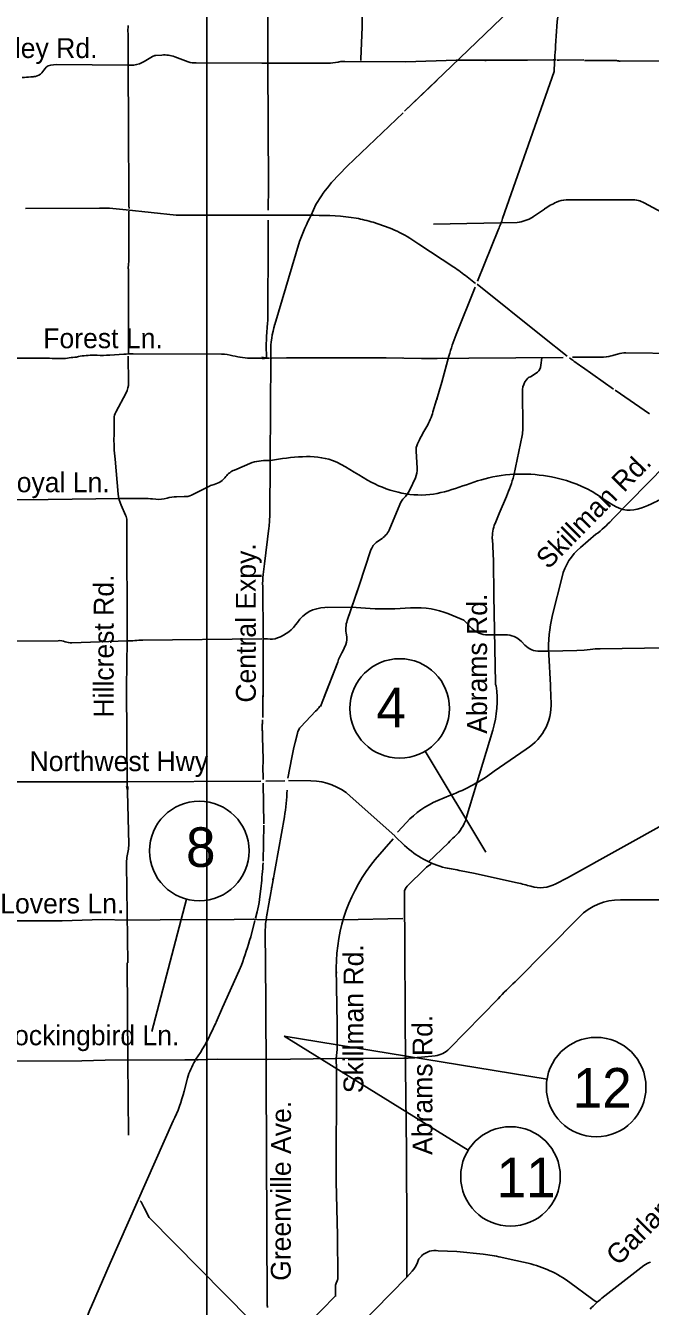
# Model space of a CAD drawing. Extents: x 105094 to 105814, y -291615 to -291123.
# Drawn here: x 105448.1 to 105486.2, y -291448 to -291369.9 of the extents above; entities that cross this region are included whole.
import ezdxf

# ---------------------------------------------------------------- set-up
doc = ezdxf.new("R2010")
doc.units = 0
doc.layers.add('G_BORDER', color=7, linetype='Continuous')
doc.layers.add('G_MAP', color=7, linetype='Continuous')

msp = doc.modelspace()

# ---------------------------------------------------------------- linework, layer by layer
at = {"layer": 'G_BORDER'}
for p, q in [((105459.139, -291158.398), (105459.139, -291578.398)), ((105476.145, -291420.288), (105472.461, -291414.129)), ((105455.785, -291431.225), (105457.913, -291423.154)), ((105463.865, -291431.513), (105479.882, -291434.137)), ((105463.865, -291431.513), (105475.077, -291438.476))]:
    msp.add_line(p, q, dxfattribs=at)
for centre in [(105470.903, -291411.525), (105458.686, -291420.219), (105482.877, -291434.627), (105477.655, -291440.078)]:
    msp.add_circle(centre, 3.035, dxfattribs=at)
at = {"layer": 'G_MAP'}
for p, q in [((105474.575, -291371.851), (105477.633, -291368.905)), ((105449.967, -291372.236), (105454.349, -291372.277)), ((105456.044, -291371.689), (105456.396, -291371.661)), ((105457.192, -291371.769), (105458.018, -291372.071)), ((105467.148, -291372.091), (105467.221, -291372.077)), ((105467.548, -291372.064), (105471.274, -291372.067)), ((105468.533, -291371.996), (105468.529, -291371.893)), ((105471.193, -291375.09), (105474.575, -291371.851)), ((105474.348, -291371.969), (105471.274, -291372.067)), ((105474.348, -291371.969), (105478.686, -291371.967)), ((105476.135, -291371.96), (105476.132, -291372.025)), ((105478.686, -291371.967), (105480.259, -291371.96)), ((105480.259, -291371.96), (105480.43, -291371.96)), ((105480.492, -291371.967), (105480.621, -291371.973)), ((105480.621, -291371.973), (105482.119, -291371.957)), ((105482.168, -291371.993), (105483.98, -291371.993)), ((105484.337, -291372.036), (105487.826, -291372.012)), ((105480.317, -291372.658), (105477.174, -291381.633)), ((105471.193, -291375.09), (105473.18, -291373.184)), ((105471.193, -291375.09), (105473.18, -291373.184)), ((105471.119, -291375.196), (105467.69, -291378.436)), ((105467.69, -291378.436), (105466.754, -291379.439)), ((105465.799, -291380.781), (105465.504, -291381.437)), ((105485.042, -291380.486), (105481.051, -291380.499)), ((105489.337, -291382.576), (105485.809, -291380.678)), ((105452.598, -291380.994), (105448.103, -291381.018)), ((105457.271, -291381.436), (105454.236, -291381.11)), ((105461.673, -291381.439), (105457.271, -291381.436)), ((105479.719, -291381.054), (105479.006, -291381.545)), ((105470.26, -291382.198), (105469.294, -291381.862)), ((105478.063, -291381.885), (105472.963, -291381.969)), ((105476.916, -291382.285), (105475.647, -291385.466)), ((105464.8, -291383.032), (105463.289, -291388.09)), ((105472.065, -291383.199), (105471.516, -291382.828)), ((105474.197, -291384.594), (105472.065, -291383.199)), ((105475.531, -291385.595), (105475.014, -291385.195)), ((105475.505, -291385.821), (105474.346, -291388.705)), ((105479.632, -291388.851), (105475.631, -291385.647)), ((105462.786, -291388.824), (105462.836, -291388.024)), ((105462.774, -291390.139), (105462.771, -291389.355)), ((105481.111, -291390.042), (105479.632, -291388.851)), ((105440.514, -291390.176), (105449.211, -291390.156)), ((105452.278, -291389.975), (105452.46, -291389.978)), ((105453.228, -291389.965), (105454.081, -291389.92)), ((105454.369, -291391.654), (105454.358, -291390.04)), ((105454.665, -291389.894), (105460.041, -291389.914)), ((105461.922, -291390.152), (105462.506, -291390.146)), ((105462.761, -291390.146), (105462.965, -291390.146)), ((105463.039, -291390.214), (105463.02, -291393.153)), ((105463.039, -291389.797), (105463.039, -291389.984)), ((105463.039, -291389.984), (105463.039, -291390.214)), ((105480.866, -291390.104), (105472.236, -291390.175)), ((105473.526, -291390.164), (105472.236, -291390.175)), ((105473.526, -291390.164), (105472.236, -291390.175)), ((105473.18, -291390.167), (105472.236, -291390.175)), ((105473.18, -291390.167), (105472.236, -291390.175)), ((105483.169, -291390.097), (105481.441, -291390.091)), ((105484.186, -291389.902), (105483.801, -291390.011)), ((105488.846, -291389.877), (105484.693, -291389.835)), ((105483.937, -291392.041), (105482.036, -291390.709)), ((105479.224, -291391.073), (105478.88, -291391.302)), ((105453.596, -291393.445), (105454.225, -291392.274)), ((105478.395, -291392.07), (105478.402, -291394.468)), ((105486.12, -291393.559), (105484.034, -291392.103)), ((105463.02, -291393.153), (105462.997, -291396.514)), ((105472.93, -291393.426), (105473.154, -291392.697)), ((105453.49, -291394.916), (105453.5, -291393.831)), ((105478.365, -291394.881), (105477.862, -291397.321)), ((105453.499, -291395.594), (105453.49, -291395.359)), ((105471.984, -291395.389), (105472.106, -291395.139)), ((105453.741, -291398.442), (105453.551, -291396.311)), ((105471.969, -291396.861), (105471.898, -291395.826)), ((105461.916, -291396.522), (105460.827, -291396.978)), ((105462.997, -291396.514), (105462.984, -291399.626)), ((105487.099, -291396.685), (105483.821, -291400.044)), ((105459.311, -291397.957), (105458.208, -291398.514)), ((105459.601, -291397.859), (105459.447, -291397.903)), ((105471.518, -291398.186), (105471.857, -291397.464)), ((105456.045, -291398.762), (105455.838, -291398.746)), ((105457.762, -291398.594), (105457.292, -291398.609)), ((105454.199, -291399.728), (105453.922, -291399.125)), ((105470.307, -291400.554), (105470.976, -291398.945)), ((105462.927, -291400.521), (105462.661, -291402.702)), ((105469.539, -291401.346), (105469.824, -291401.149)), ((105482.865, -291400.9), (105481.919, -291401.697)), ((105462.661, -291402.702), (105462.587, -291403.351)), ((105480.798, -291403.496), (105480.22, -291405.821)), ((105462.552, -291404.081), (105462.574, -291407.185)), ((105467.951, -291405.35), (105466.34, -291405.372)), ((105467.951, -291405.35), (105466.495, -291405.37)), ((105467.951, -291405.35), (105466.495, -291405.37)), ((105474.814, -291406.144), (105475.305, -291406.638)), ((105450.086, -291407.395), (105442.801, -291407.424)), ((105454.31, -291407.401), (105450.91, -291407.522)), ((105462.503, -291407.285), (105455.244, -291407.355)), ((105462.574, -291407.385), (105462.57, -291410.814)), ((105462.574, -291407.185), (105462.574, -291407.385)), ((105462.852, -291407.285), (105462.639, -291407.285)), ((105476.261, -291407.033), (105477.329, -291407.026)), ((105467.415, -291408.063), (105467.61, -291407.619)), ((105467.415, -291408.063), (105467.61, -291407.619)), ((105467.415, -291408.063), (105467.61, -291407.619)), ((105478.323, -291407.445), (105478.534, -291407.664)), ((105466.075, -291411.399), (105467.121, -291408.693)), ((105466.301, -291410.814), (105467.121, -291408.693)), ((105466.301, -291410.814), (105467.121, -291408.693)), ((105479.99, -291408.242), (105480.091, -291410.11)), ((105462.572, -291409.355), (105462.568, -291412.077)), ((105462.572, -291409.355), (105462.57, -291410.814)), ((105454.249, -291410.25), (105454.294, -291416.292)), ((105454.249, -291410.25), (105454.253, -291410.814)), ((105454.249, -291410.25), (105454.253, -291410.814)), ((105480.104, -291410.879), (105480.091, -291410.111)), ((105465.765, -291411.696), (105464.874, -291412.655)), ((105476.57, -291412.845), (105474.956, -291418.222)), ((105476.658, -291415.361), (105478.609, -291414.002)), ((105462.568, -291415.035), (105462.574, -291415.865)), ((105463.898, -291415.936), (105462.742, -291415.959)), ((105465.494, -291415.943), (105464.128, -291415.93)), ((105454.317, -291416.618), (105454.389, -291419.795)), ((105462.578, -291416.091), (105462.616, -291418.558)), ((105473.218, -291417.143), (105474, -291416.814)), ((105470.609, -291419.288), (105467.887, -291416.867)), ((105463.876, -291418.131), (105462.778, -291424.248)), ((105487.451, -291418.332), (105481.125, -291421.859)), ((105462.613, -291418.652), (105462.574, -291420.838)), ((105470.771, -291419.081), (105471.326, -291418.475)), ((105469.411, -291420.748), (105470.512, -291419.485)), ((105470.6, -291419.32), (105471.203, -291419.89)), ((105473.874, -291419.73), (105472.637, -291420.909)), ((105454.254, -291421.023), (105454.336, -291427.049)), ((105471.358, -291422.372), (105472.446, -291421.291)), ((105474.643, -291421.429), (105475.408, -291421.577)), ((105463.136, -291421.949), (105463.207, -291421.969)), ((105475.408, -291421.577), (105478.068, -291422.162)), ((105480.423, -291422.227), (105481.125, -291421.859)), ((105462.453, -291422.355), (105462.356, -291423.179)), ((105463.13, -291422.508), (105463.046, -291422.495)), ((105471.252, -291433.468), (105471.187, -291422.773)), ((105462.93, -291423.147), (105462.991, -291423.17)), ((105484.35, -291423.199), (105486.735, -291423.209)), ((105461.983, -291424.391), (105460.814, -291424.397)), ((105462.077, -291424.462), (105461.822, -291425.466)), ((105462.203, -291424.397), (105461.974, -291424.391)), ((105462.212, -291423.936), (105462.109, -291424.329)), ((105467.464, -291424.416), (105462.2, -291424.397)), ((105462.862, -291424.039), (105462.775, -291424.009)), ((105471.1, -291424.338), (105467.461, -291424.416)), ((105477.94, -291428.214), (105481.852, -291424.24)), ((105462.704, -291425.059), (105462.752, -291429.393)), ((105461.111, -291427.52), (105460.094, -291429.774)), ((105461.254, -291427.178), (105461.111, -291427.52)), ((105467.083, -291427.636), (105466.983, -291427.655)), ((105473.924, -291432.294), (105476.897, -291429.238)), ((105460.094, -291429.774), (105459.707, -291430.675)), ((105462.752, -291429.393), (105462.82, -291447.834)), ((105457.811, -291432.971), (105458.315, -291432.965)), ((105458.315, -291432.965), (105458.612, -291432.968)), ((105458.754, -291432.519), (105458.486, -291432.92)), ((105458.612, -291432.968), (105459.791, -291432.932)), ((105472.226, -291432.797), (105473.067, -291432.709)), ((105457.969, -291434.082), (105457.756, -291434.87)), ((105457.094, -291436.692), (105453.264, -291445.373)), ((105472.25, -291444.91), (105472.224, -291444.935)), ((105453.264, -291445.373), (105452.115, -291447.991)), ((105483.231, -291447.504), (105485.79, -291445.517)), ((105467.034, -291446.583), (105467.097, -291446.441)), ((105466.993, -291447.397), (105466.993, -291446.845)), ((105481.274, -291446.541), (105482.601, -291447.526)), ((105466.992, -291447.365), (105465.239, -291449.141))]:
    msp.add_line(p, q, dxfattribs=at)
for points in [[(105462.887, -291381.123), (105462.907, -291379.702), (105462.862, -291372.19), (105462.839, -291365.796)], [(105468.529, -291371.893), (105468.607, -291369.965), (105468.594, -291367.264)], [(105454.388, -291380.316), (105454.368, -291376.159), (105454.342, -291372.239), (105454.342, -291370.34)], [(105455.036, -291372.188), (105455.127, -291372.155), (105455.337, -291372.045), (105455.825, -291371.758)], [(105458.492, -291372.129), (105462.494, -291372.164), (105466.521, -291372.151)], [(105454.388, -291384.285), (105454.391, -291383.736), (105454.394, -291381.188)], [(105462.868, -291387.343), (105462.894, -291383.164), (105462.884, -291381.727)], [(105454.362, -291389.927), (105454.368, -291385.557), (105454.362, -291384.711)], [(105449.886, -291390.182), (105450.541, -291390.169), (105450.871, -291390.117)], [(105463.104, -291390.146), (105463.998, -291390.133), (105470.086, -291390.13), (105471.08, -291390.15)], [(105469.837, -291390.13), (105470.086, -291390.13), (105471.08, -291390.15)], [(105469.837, -291390.13), (105470.086, -291390.13), (105472.236, -291390.175)], [(105473.901, -291390.025), (105473.46, -291391.628), (105473.147, -291392.726)], [(105473.223, -291392.46), (105473.147, -291392.726)], [(105473.223, -291392.46), (105473.147, -291392.726)], [(105473.18, -291392.613), (105473.147, -291392.726)], [(105473.18, -291392.613), (105473.147, -291392.726)], [(105455.298, -291398.714), (105453.848, -291398.724), (105449.472, -291398.776), (105443.595, -291398.798)], [(105477.42, -291398.587), (105476.955, -291399.634), (105476.713, -291400.232)], [(105454.249, -291410.25), (105454.294, -291407.398), (105454.271, -291400.069)], [(105467.704, -291406.154), (105468.442, -291403.971), (105469.126, -291401.899)], [(105476.548, -291401.202), (105476.609, -291402.524), (105476.648, -291404.636), (105476.732, -291409.977)], [(105467.704, -291406.154), (105468.34, -291404.273)], [(105467.704, -291406.154), (105468.34, -291404.273)], [(105479.44, -291408.039), (105479.988, -291408.027), (105481.699, -291407.982), (105482.148, -291407.959), (105482.52, -291407.927)], [(105483.13, -291407.888), (105487.173, -291407.827), (105488.485, -291407.785), (105493.093, -291407.704), (105495.115, -291407.662), (105497.033, -291407.681)], [(105464.668, -291413.025), (105464.451, -291413.911), (105464.318, -291414.518), (105464.092, -291415.788)], [(105464.668, -291413.025), (105464.524, -291413.613)], [(105464.668, -291413.025), (105464.524, -291413.613)], [(105462.448, -291415.962), (105454.301, -291416.011), (105442.268, -291416.005)], [(105460.814, -291424.397), (105456.296, -291424.413), (105454.3, -291424.436), (105452.77, -291424.404), (105450.331, -291424.488), (105445.991, -291424.491)], [(105454.362, -291437.561), (105454.323, -291432.997), (105454.291, -291427.039)], [(105467.054, -291433.555), (105467.038, -291432.89), (105467.093, -291432.335), (105467.092, -291430.791), (105467.038, -291427.345)], [(105441.075, -291433.014), (105441.566, -291433.046), (105451.529, -291433.03), (105452.947, -291432.988), (105457.811, -291432.971)], [(105459.791, -291432.932), (105462.836, -291432.939), (105467.021, -291432.884), (105471.146, -291432.864)], [(105467.132, -291446.245), (105467.118, -291443.68), (105467.034, -291440.376), (105467.054, -291433.555)], [(105471.339, -291446.199), (105471.327, -291443.641), (105471.307, -291438.535), (105471.252, -291433.468)], [(105455.331, -291442.001), (105455.15, -291441.63), (105455.085, -291441.575)], [(105462.839, -291449.907), (105461.796, -291448.822), (105455.634, -291442.573), (105455.331, -291442.001)], [(105473.251, -291444.623), (105474.385, -291444.652), (105475.993, -291444.816)], [(105477.072, -291445.001), (105477.695, -291445.136), (105478.727, -291445.377)], [(105471.669, -291445.853), (105471.33, -291446.221), (105468.414, -291449.206), (105465.61, -291451.938), (105463.22, -291454.38), (105458.379, -291459.237), (105456.07, -291461.521)]]:
    msp.add_lwpolyline(points, dxfattribs=at)
for centre, radius, start, end in [((105456.987, -291370.192), 2.649, 172.90765, 183.19615), ((105454.476, -291370.637), 1.648, 265.57828, 289.84555), ((105456.085, -291372.2), 0.512, 94.60671, 120.42732), ((105456.548, -291373.53), 1.876, 69.90353, 94.63636), ((105458.358, -291371.256), 0.883, 247.31491, 278.72622), ((105466.509, -291368.734), 3.417, 270.19641, 280.77032), ((105467.407, -291372.647), 0.6, 76.48657, 108.05496), ((105483.979, -291373.11), 1.117, 76.96772, 89.90709), ((105484.335, -291371.657), 0.379, 254.0581, 270.35405), ((105447.854, -291368.986), 4.039, 270.59303, 278.00387), ((105473.216, -291385.048), 8.557, 139.03718, 150.08606), ((105461.352, -291380.479), 6.966, 178.65839, 184.48031), ((105482.347, -291384.866), 4.631, 114.06028, 124.5774), ((105481.057, -291381.858), 1.358, 90.24609, 116.09824), ((105485.047, -291382.093), 1.608, 61.71655, 90.19845), ((105452.658, -291391.793), 10.799, 81.59999, 90.31773), ((105475.855, -291386.965), 11.734, 151.89398, 160.4146), ((105473.209, -291380.439), 4.141, 333.53368, 343.25265), ((105477.661, -291379.286), 2.63, 278.79374, 300.7632), ((105466.271, -291391.723), 10.327, 59.47499, 67.27768), ((105456.631, -291384.635), 2.271, 171.13441, 181.92475), ((105466.219, -291396.302), 14.167, 51.62792, 55.72999), ((105459.104, -291387.506), 3.768, 352.09201, 2.48086), ((105469.007, -291389.797), 5.968, 163.37288, 179.99929), ((105470.949, -291389.33), 8.178, 176.44883, 180.17709), ((105485.723, -291393.275), 12.26, 158.11332, 164.62616), ((105449.099, -291401.924), 11.769, 86.16477, 89.45362), ((105450.848, -291388.203), 1.914, 270.69247, 284.1748), ((105452.187, -291394.458), 4.485, 88.82709, 101.18931), ((105452.764, -291385.221), 4.767, 266.33968, 275.58838), ((105454.576, -291394.499), 4.606, 88.89074, 96.17397), ((105460.037, -291392.665), 2.751, 75.23863, 89.9255), ((105461.877, -291385.681), 4.471, 255.24282, 270.58222), ((105462.509, -291390.486), 0.383, 70.79201, 90.00362), ((105462.509, -291389.806), 0.383, 270.00369, 289.21531), ((105462.761, -291389.763), 0.383, 250.79211, 270.00372), ((105462.761, -291390.529), 0.383, 90.00365, 109.21526), ((105474.054, -291389.668), 5.526, 348.92208, 355.24674), ((105494.064, -291373.555), 20.951, 232.30477, 234.96455), ((105483.177, -291387.801), 2.296, 269.78609, 285.76707), ((105484.674, -291391.631), 1.796, 89.40072, 105.76144), ((105478.879, -291390.554), 0.623, 303.54832, 343.59133), ((105453.143, -291391.694), 1.227, 331.83134, 1.88438), ((105479.309, -291392.086), 0.914, 138.19423, 179.02054), ((105478.922, -291391.633), 0.334, 97.36085, 152.02943), ((105454.31, -291393.828), 0.811, 151.85089, 180.22784), ((105467.808, -291391.856), 5.357, 332.48801, 342.96051), ((105460.639, -291395.137), 7.153, 178.22966, 181.77441), ((105479.291, -291398.643), 7.994, 147.35889, 154.00196), ((105476.595, -291394.515), 1.807, 348.33204, 1.50301), ((105464.726, -291395.146), 11.235, 182.28917, 185.95544), ((105472.76, -291395.768), 0.864, 154.00761, 183.88157), ((105462.854, -291399.817), 3.426, 87.11339, 105.899), ((105461.33, -291398.176), 1.299, 112.74899, 142.17138), ((105470.753, -291396.946), 1.219, 334.85905, 4.01293), ((105459.664, -291398.657), 0.784, 106.08977, 116.78922), ((105459.225, -291396.554), 1.358, 286.08478, 322.60226), ((105464.016, -291393.193), 14.449, 338.07599, 343.39581), ((105455.817, -291398.256), 2.084, 185.09516, 204.61278), ((105455.366, -291402.099), 3.386, 81.99849, 91.15104), ((105456.193, -291396.787), 1.98, 265.71015, 285.43324), ((105457.371, -291401.063), 2.455, 91.84194, 105.38441), ((105457.87, -291397.919), 0.684, 260.93851, 299.59859), ((105471.638, -291399.221), 0.717, 133.32181, 157.377), ((105469.985, -291397.466), 1.694, 313.27668, 334.86937), ((105455.087, -291399.568), 7.897, 353.07253, 359.58061), ((105453.48, -291400.058), 0.791, 359.21568, 24.65603), ((105478.847, -291401.095), 2.302, 157.98058, 182.67386), ((105477.381, -291393.812), 8.962, 307.73254, 315.94253), ((105469.054, -291400.032), 1.357, 304.584, 337.38831), ((105470.155, -291402.238), 1.084, 124.60637, 161.75987), ((105484.131, -291404.323), 3.434, 130.11499, 166.05589), ((105466.187, -291403.892), 3.64, 171.45435, 182.97493), ((105466.368, -291407.425), 2.054, 90.78567, 145.9361), ((105488.183, -291407.8), 8.205, 166.04431, 183.09138), ((105462.592, -291404.872), 2.505, 290.17392, 325.93594), ((105469.224, -291406.668), 1.605, 161.32798, 193.38978), ((105469.224, -291406.668), 1.605, 161.32798, 193.38978), ((105469.224, -291406.668), 1.605, 161.32798, 193.38978), ((105476.253, -291405.695), 1.337, 224.8513, 270.34399), ((105450.198, -291408.225), 0.837, 67.46724, 97.69655), ((105454.453, -291405.005), 2.401, 266.58731, 277.09845), ((105455.27, -291411.552), 4.198, 90.35695, 97.11919), ((105463.045, -291406.185), 1.117, 260.03333, 291.57314), ((105466.776, -291407.251), 0.912, 336.24808, 13.40225), ((105466.776, -291407.251), 0.912, 336.24808, 13.40225), ((105466.776, -291407.251), 0.912, 336.24808, 13.40225), ((105477.338, -291408.392), 1.366, 43.89807, 90.36509), ((105450.878, -291406.587), 0.936, 247.47718, 271.99599), ((105469.769, -291409.545), 2.781, 147.80898, 162.16191), ((105469.769, -291409.545), 2.781, 147.80898, 162.16191), ((105469.769, -291409.545), 2.781, 147.80898, 162.16191), ((105479.414, -291406.817), 1.222, 223.89247, 271.22299), ((105483.039, -291411.274), 3.387, 88.45449, 98.81442), ((105470.412, -291410.997), 6.43, 343.29267, 7.66313), ((105477.008, -291409.978), 0.276, 179.87024, 215.72931), ((105476.957, -291411.292), 3.174, 301.35754, 7.46798), ((105465.036, -291410.761), 1.186, 307.94073, 327.81268), ((105482.509, -291412.654), 19.981, 178.75432, 182.99685), ((105482.509, -291412.654), 19.981, 178.75432, 182.19431), ((105482.509, -291412.654), 19.981, 178.75432, 182.19431), ((105465.439, -291413.212), 0.794, 135.39347, 166.31756), ((105465.439, -291413.212), 0.794, 135.39347, 166.31756), ((105465.439, -291413.212), 0.794, 135.39347, 166.31756), ((105437.774, -291414.606), 24.798, 359.00816, 2.09767), ((105465.458, -291419.598), 3.655, 48.34842, 89.44205), ((105470.222, -291406.746), 10.754, 290.56899, 306.76143), ((105454.888, -291416.251), 0.638, 183.96491, 198.8223), ((105453.681, -291416.662), 0.638, 3.96485, 18.82224), ((105454.953, -291416.574), 0.638, 169.10755, 183.96494), ((105453.701, -291416.333), 0.638, 349.10746, 3.96485), ((105453.916, -291416.342), 10.12, 349.81782, 359.00696), ((105475.316, -291422.133), 5.413, 112.8069, 137.48618), ((105472.696, -291417.571), 2.353, 310.88321, 343.92179), ((105452.791, -291419.836), 1.599, 346.61188, 1.49709), ((105475.046, -291415.816), 5.6, 226.66775, 255.92269), ((105475.996, -291421.382), 2.689, 130.89232, 142.0945), ((105457.625, -291420.99), 3.371, 166.56736, 180.5649), ((105439.795, -291419.687), 22.814, 353.28374, 356.83907), ((105477.341, -291427.326), 10.303, 140.31955, 180.1064), ((105473.444, -291422.295), 1.416, 115.94892, 134.81454), ((105471.132, -291437.415), 16.367, 77.61161, 81.02915), ((105475.423, -291434.123), 12.249, 73.51415, 77.53171), ((105479.477, -291420.427), 2.034, 253.48533, 297.71202), ((105471.769, -291422.785), 0.582, 134.85304, 178.86316), ((105456.862, -291422.532), 5.531, 345.29163, 353.27819), ((105484.336, -291426.685), 3.485, 89.75986, 135.45428), ((105471.822, -291425.486), 9.128, 172.20856, 177.31954), ((105436.375, -291417.966), 26.529, 339.68147, 343.57725), ((105484.995, -291436.446), 10.841, 130.59496, 138.32526), ((105445.907, -291424.714), 15.032, 328.71834, 336.63619), ((105472.922, -291431.319), 1.398, 275.95994, 315.77442), ((105462.384, -291435.35), 4.593, 149.46584, 163.96966), ((105470.981, -291421.454), 11.411, 270.82668, 276.26367), ((105449.501, -291432.901), 8.486, 333.46841, 346.58179), ((105472.851, -291445.604), 0.917, 133.15148, 162.01807), ((105473.032, -291445.745), 1.144, 78.94796, 133.13375), ((105474.416, -291457.306), 12.589, 77.82187, 82.80391), ((105470.614, -291444.882), 1.434, 317.38607, 342.16211), ((105477.13, -291452.235), 7.042, 53.95919, 76.89268), ((105486.525, -291446.441), 1.181, 107.02262, 128.47148), ((105466.701, -291446.269), 0.431, 336.51562, 3.22901), ((105467.426, -291446.78), 0.438, 153.28963, 188.47448), ((105466.386, -291454.248), 15.582, 156.3243, 163.25405), ((105463.665, -291447.84), 0.844, 179.53905, 195.37593), ((105486.614, -291451.853), 5.51, 127.87873, 138.00905), ((105483.235, -291446.89), 0.899, 225.0986, 251.24528)]:
    msp.add_arc(centre, radius, start, end, dxfattribs=at)
for points in [[(105485.111, -291359.381), (105481.067, -291366.438), (105480.399, -291371.098), (105480.317, -291372.658)], [(105449.967, -291372.236), (105449.354, -291372.405), (105449.088, -291372.755), (105448.696, -291372.963), (105448.416, -291372.985)], [(105469.294, -291381.862), (105468.252, -291381.616), (105465.675, -291381.437), (105461.673, -291381.439)], [(105463.027, -291396.395), (105466.797, -291396.395), (105468.945, -291397.601), (105472.732, -291398.475), (105476.336, -291397.455), (105480.413, -291397.455), (105482.925, -291398.475), (105484.746, -291399.423), (105486.457, -291398.949), (105487.284, -291398.616), (105488.378, -291398.636)], [(105474.814, -291406.144), (105472.827, -291405.452), (105470.279, -291405.452), (105467.951, -291405.35)]]:
    msp.add_spline(points, degree=3, dxfattribs=at)

# ---------------------------------------------------------------- texts
at = {"layer": 'G_BORDER'}
for s, p in [('4', (105469.484, -291412.67)), ('8', (105457.879, -291421.194)), ('12', (105481.45, -291435.879)), ('11', (105476.809, -291441.348))]:
    msp.add_text(s, height=2.416, dxfattribs=at).set_placement(p)
at = {"layer": 'G_MAP'}
for s, height, p in [('Spring Valley Rd.', 1.21107, (105439.971, -291371.842)), ('Forest Ln.', 1.2111, (105449.174, -291389.545)), ('Royal Ln.', 1.2111, (105446.389, -291398.334)), ('Northwest Hwy', 1.21107, (105448.339, -291415.349)), ('Lovers Ln.', 1.2111, (105446.554, -291424.029)), ('Mockingbird Ln.', 1.21107, (105446.045, -291432.074))]:
    msp.add_text(s, height=height, dxfattribs=at).set_placement(p)
for s, height, rotation, p in [('Skillman Rd.', 1.21107, 45.49919, (105479.96, -291403.08)), ('Central Expy.', 1.21107, 90, (105462.133, -291411.169)), ('Hillcrest Rd.', 1.21107, 90, (105453.468, -291412.082)), ('Abrams Rd.', 1.2111, 90, (105476.225, -291413.07)), ('Skillman Rd.', 1.21107, 90, (105468.69, -291435.001)), ('Abrams Rd.', 1.2111, 90, (105472.895, -291438.763)), ('Greenville Ave.', 1.21107, 89.90288, (105464.259, -291446.447)), ('Garland Rd.', 1.21107, 45.55826, (105484.224, -291445.583))]:
    msp.add_text(s, height=height, rotation=rotation, dxfattribs=at).set_placement(p)

doc.saveas('drawing.dxf')
